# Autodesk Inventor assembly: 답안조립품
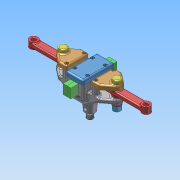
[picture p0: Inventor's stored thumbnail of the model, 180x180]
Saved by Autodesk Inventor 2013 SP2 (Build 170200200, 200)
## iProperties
Created: 2025-07
Part Number: 답안조립품
Document SubType Name: Assembly
Designer: a
Author: a
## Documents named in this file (11)
- C:\Users\a\Desktop\750703V1005\답안조립품.iam
- C:\Users\a\Desktop\750703V1005\본체.ipt
- C:\Users\a\Desktop\750703V1005\6각 구멍붙이 볼트 M3x10.ipt
- C:\Users\a\Desktop\750703V1005\6각 너트 M8.ipt
- C:\Users\a\Desktop\750703V1005\링크 커버.ipt
- C:\Users\a\Desktop\750703V1005\링크.ipt
- C:\Users\a\Desktop\750703V1005\스프링 와셔 M8.ipt
- C:\Users\a\Desktop\750703V1005\슬라이더 커버.ipt
- C:\Users\a\Desktop\750703V1005\슬라이더.ipt
- C:\Users\a\Desktop\750703V1005\평 와셔 M8.ipt
- C:\Users\a\Desktop\750703V1005\핀.ipt
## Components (12 placed, 3 different names)
1. 6각 구멍붙이 볼트 M3x10:1
2. 6각 너트 M8:1
3. 핀:1 — 각도:3
4. 핀:2 — 각도:4
5. 6각 너트 M8:2
6. 6각 구멍붙이 볼트 M3x10:2
7. 6각 구멍붙이 볼트 M3x10:3
8. 6각 구멍붙이 볼트 M3x10:4
9. 6각 구멍붙이 볼트 M3x10:5
10. 6각 구멍붙이 볼트 M3x10:6
11. 6각 구멍붙이 볼트 M3x10:7
12. 6각 구멍붙이 볼트 M3x10:8
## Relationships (2: Angle 2)
- 각도:3 [Angle]: 핀:1
- 각도:4 [Angle]: 핀:2
